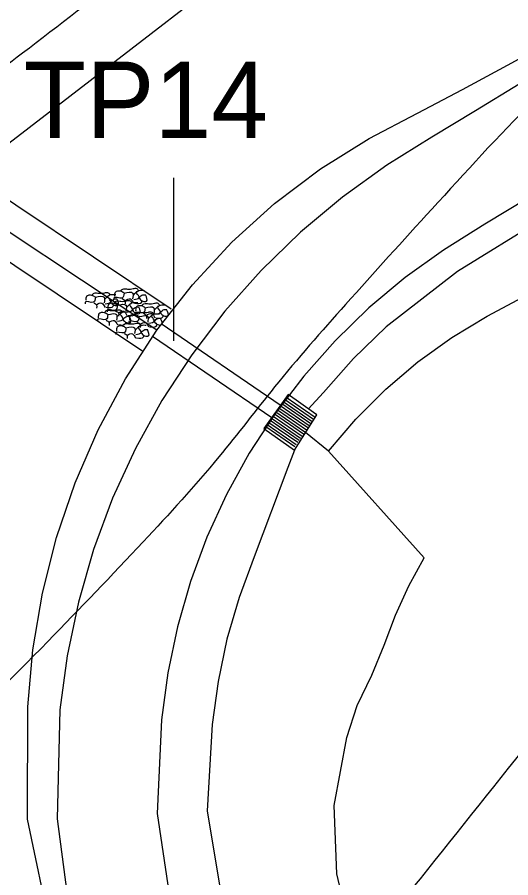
# Model space of a CAD drawing. Extents: x -478000 to -474772, y -1116847 to -1114124.
# Drawn here: x -476765.72 to -476746.36, y -1114902.02 to -1114868.23 of the extents above; entities that cross this region are included whole.
import ezdxf

# ---------------------------------------------------------------- set-up
doc = ezdxf.new("R2010")
doc.units = 0
for name, color, linetype in [('cestn___p____kop', 7, 'Continuous'), ('dren____', 7, 'Continuous'), ('hrana_L', 7, 'Continuous'), ('RozhraniKultur', 7, 'Continuous'), ('TP _navrh', 7, 'Continuous'), ('Vrstevnice_hlavni', 7, 'Continuous'), ('Vrstevnice_vedlejsi', 7, 'Continuous'), ('ZNACKY', 7, 'Continuous')]:
    doc.layers.add(name, color=color, linetype=linetype)

msp = doc.modelspace()

# ---------------------------------------------------------------- linework, layer by layer
at = {"layer": 'cestn___p____kop'}
for p, q in [((-476745.668, -1114875.318), (-476747.377, -1114876.357)), ((-476747.377, -1114876.357), (-476749.008, -1114877.372)), ((-476749.008, -1114877.372), (-476750.511, -1114878.453)), ((-476750.511, -1114878.453), (-476751.93, -1114879.641)), ((-476747.289, -1114879.961), (-476745.696, -1114879.121)), ((-476747.289, -1114879.961), (-476745.696, -1114879.121)), ((-476751.93, -1114879.641), (-476753.258, -1114880.932)), ((-476748.682, -1114880.808), (-476747.289, -1114879.961)), ((-476748.682, -1114880.808), (-476747.289, -1114879.961)), ((-476753.258, -1114880.932), (-476754.486, -1114882.317)), ((-476750.014, -1114881.764), (-476748.682, -1114880.808)), ((-476750.014, -1114881.764), (-476748.682, -1114880.808)), ((-476751.268, -1114882.833), (-476750.014, -1114881.764)), ((-476751.268, -1114882.833), (-476750.014, -1114881.764)), ((-476754.486, -1114882.317), (-476755.609, -1114883.79)), ((-476752.436, -1114884.004), (-476751.268, -1114882.833)), ((-476752.436, -1114884.004), (-476751.268, -1114882.833)), ((-476755.609, -1114883.79), (-476756.619, -1114885.341)), ((-476753.509, -1114885.27), (-476752.436, -1114884.004)), ((-476753.509, -1114885.27), (-476752.436, -1114884.004)), ((-476756.619, -1114885.341), (-476757.512, -1114886.963)), ((-476754.844, -1114885.23), (-476755.107, -1114885.904)), ((-476749.758, -1114889.456), (-476753.509, -1114885.27)), ((-476749.758, -1114889.456), (-476753.509, -1114885.27)), ((-476755.107, -1114885.904), (-476756.431, -1114889.412)), ((-476757.512, -1114886.963), (-476758.282, -1114888.647)), ((-476758.282, -1114888.647), (-476758.926, -1114890.383)), ((-476756.431, -1114889.412), (-476757.023, -1114891.009)), ((-476750.365, -1114890.559), (-476749.758, -1114889.456)), ((-476750.365, -1114890.559), (-476749.758, -1114889.456)), ((-476758.926, -1114890.383), (-476759.439, -1114892.162)), ((-476750.889, -1114891.704), (-476750.365, -1114890.559)), ((-476750.889, -1114891.704), (-476750.365, -1114890.559)), ((-476757.023, -1114891.009), (-476757.495, -1114892.645)), ((-476751.327, -1114892.884), (-476750.889, -1114891.704)), ((-476751.327, -1114892.884), (-476750.889, -1114891.704)), ((-476759.439, -1114892.162), (-476759.819, -1114893.973)), ((-476757.495, -1114892.645), (-476757.845, -1114894.312)), ((-476751.813, -1114894.06), (-476751.327, -1114892.884)), ((-476751.813, -1114894.06), (-476751.327, -1114892.884)), ((-476759.819, -1114893.973), (-476760.064, -1114895.809)), ((-476752.392, -1114895.247), (-476751.813, -1114894.06)), ((-476752.392, -1114895.247), (-476751.813, -1114894.06)), ((-476757.845, -1114894.312), (-476758.071, -1114896)), ((-476752.796, -1114896.507), (-476752.392, -1114895.247)), ((-476752.796, -1114896.507), (-476752.392, -1114895.247)), ((-476752.869, -1114903.183), (-476753.187, -1114901.86)), ((-476752.869, -1114903.183), (-476753.187, -1114901.86))]:
    msp.add_line(p, q, dxfattribs=at)
for points in [[(-476746.491, -1114870.118), (-476744.735, -1114869.156)], [(-476748.258, -1114871.062), (-476746.491, -1114870.118)], [(-476750.028, -1114872), (-476748.258, -1114871.062)], [(-476746.039, -1114870.861), (-476747.747, -1114871.9)], [(-476751.917, -1114872.99), (-476750.028, -1114872)], [(-476747.747, -1114871.9), (-476749.456, -1114872.94)], [(-476753.822, -1114874.188), (-476751.917, -1114872.99)], [(-476749.456, -1114872.94), (-476751.22, -1114874.04)], [(-476755.626, -1114875.548), (-476753.822, -1114874.188)], [(-476751.22, -1114874.04), (-476752.964, -1114875.293)], [(-476757.305, -1114877.067), (-476755.626, -1114875.548)], [(-476752.964, -1114875.293), (-476754.611, -1114876.672)], [(-476745.145, -1114876.177), (-476748.451, -1114878.211)], [(-476754.611, -1114876.672), (-476756.15, -1114878.169)], [(-476758.846, -1114878.731), (-476757.305, -1114877.067)], [(-476756.15, -1114878.169), (-476757.575, -1114879.776)], [(-476748.451, -1114878.211), (-476751.256, -1114880.389)], [(-476760.243, -1114880.521), (-476758.846, -1114878.731)], [(-476757.575, -1114879.776), (-476758.877, -1114881.484)], [(-476761.472, -1114882.431), (-476760.243, -1114880.521)], [(-476751.256, -1114880.389), (-476752.53, -1114881.627)], [(-476758.877, -1114881.484), (-476760.049, -1114883.284)], [(-476752.53, -1114881.627), (-476753.709, -1114882.957)], [(-476762.544, -1114884.431), (-476761.472, -1114882.431)], [(-476753.709, -1114882.957), (-476754.306, -1114883.614)], [(-476760.049, -1114883.284), (-476761.085, -1114885.165)], [(-476763.443, -1114886.513), (-476762.544, -1114884.431)], [(-476761.085, -1114885.165), (-476761.978, -1114887.118)], [(-476764.177, -1114888.654), (-476763.443, -1114886.513)], [(-476761.978, -1114887.118), (-476762.725, -1114889.132)], [(-476764.727, -1114890.846), (-476764.177, -1114888.654)], [(-476762.725, -1114889.132), (-476763.321, -1114891.196)], [(-476765.113, -1114893.066), (-476764.727, -1114890.846)], [(-476763.321, -1114891.196), (-476763.762, -1114893.297)], [(-476765.309, -1114895.305), (-476765.113, -1114893.066)], [(-476763.762, -1114893.297), (-476764.046, -1114895.426)], [(-476764.384, -1114904.135), (-476765.317, -1114899.72), (-476765.309, -1114895.305)], [(-476764.046, -1114895.426), (-476764.16, -1114899.701), (-476763.598, -1114903.976)], [(-476760.064, -1114895.809), (-476760.237, -1114899.494), (-476759.678, -1114903.179)], [(-476758.071, -1114896), (-476758.265, -1114899.39), (-476757.715, -1114902.78)], [(-476753.187, -1114901.86), (-476753.292, -1114899.184), (-476752.796, -1114896.507)], [(-476753.187, -1114901.86), (-476753.292, -1114899.184), (-476752.796, -1114896.507)]]:
    msp.add_lwpolyline(points, dxfattribs=at)
at = {"layer": 'dren____'}
for points in [[(-476761.672, -1114878.983), (-476761.582, -1114878.903), (-476761.39, -1114878.903), (-476761.169, -1114878.883), (-476761.033, -1114878.883), (-476760.976, -1114878.976), (-476761.05, -1114879.015)], [(-476762.653, -1114879.223), (-476762.73, -1114879.421), (-476763.054, -1114879.421), (-476763.054, -1114879.477)], [(-476762.653, -1114879.223), (-476762.789, -1114879.151), (-476763.002, -1114879.195), (-476763.026, -1114879.344)], [(-476762.791, -1114879.146), (-476762.702, -1114879.066), (-476762.51, -1114879.066), (-476762.289, -1114879.046), (-476762.152, -1114879.046), (-476762.096, -1114879.139), (-476762.17, -1114879.178)], [(-476762.653, -1114879.223), (-476762.314, -1114879.223), (-476762.314, -1114879.445)], [(-476762.282, -1114879.3), (-476762.052, -1114879.119), (-476761.855, -1114879.119)], [(-476762.27, -1114879.477), (-476762.056, -1114879.401), (-476762.161, -1114879.227)], [(-476761.533, -1114879.06), (-476761.611, -1114879.258), (-476761.934, -1114879.258), (-476761.934, -1114879.314)], [(-476761.533, -1114879.06), (-476761.669, -1114878.988), (-476761.882, -1114879.032), (-476761.906, -1114879.181)], [(-476761.533, -1114879.06), (-476761.194, -1114879.06), (-476761.194, -1114879.282)], [(-476761.498, -1114879.357), (-476761.283, -1114879.29), (-476761.158, -1114879.459)], [(-476761.162, -1114879.137), (-476760.933, -1114878.956), (-476760.736, -1114878.956)], [(-476761.15, -1114879.314), (-476760.937, -1114879.237), (-476761.041, -1114879.064)], [(-476760.943, -1114879.248), (-476760.788, -1114879.129), (-476760.691, -1114879.129)], [(-476760.943, -1114879.248), (-476760.8, -1114879.374), (-476760.647, -1114879.374), (-476760.691, -1114879.129)], [(-476762.72, -1114879.441), (-476762.608, -1114879.537), (-476762.608, -1114879.646)], [(-476762.618, -1114879.52), (-476762.402, -1114879.453), (-476762.278, -1114879.622)], [(-476762.237, -1114879.618), (-476761.96, -1114879.575), (-476761.944, -1114879.529)], [(-476761.794, -1114879.539), (-476761.871, -1114879.737), (-476762.195, -1114879.737), (-476762.195, -1114879.793)], [(-476761.794, -1114879.539), (-476761.93, -1114879.467), (-476762.143, -1114879.511), (-476762.167, -1114879.66)], [(-476762.063, -1114879.411), (-476761.908, -1114879.292), (-476761.811, -1114879.292)], [(-476762.063, -1114879.411), (-476761.92, -1114879.537), (-476761.767, -1114879.537), (-476761.811, -1114879.292)], [(-476761.932, -1114879.462), (-476761.842, -1114879.382), (-476761.651, -1114879.382), (-476761.43, -1114879.362), (-476761.293, -1114879.362), (-476761.236, -1114879.455), (-476761.31, -1114879.494)], [(-476761.794, -1114879.539), (-476761.455, -1114879.539), (-476761.455, -1114879.761)], [(-476761.601, -1114879.278), (-476761.488, -1114879.374), (-476761.488, -1114879.483)], [(-476761.423, -1114879.616), (-476761.193, -1114879.435), (-476760.996, -1114879.435)], [(-476761.41, -1114879.793), (-476761.197, -1114879.716), (-476761.302, -1114879.543)], [(-476761.204, -1114879.727), (-476761.048, -1114879.608), (-476760.952, -1114879.608)], [(-476761.204, -1114879.727), (-476761.06, -1114879.853), (-476760.908, -1114879.853), (-476760.952, -1114879.608)], [(-476761.118, -1114879.455), (-476760.84, -1114879.412), (-476760.825, -1114879.366)], [(-476760.702, -1114879.638), (-476760.839, -1114879.565), (-476761.052, -1114879.61), (-476761.075, -1114879.759)], [(-476760.841, -1114879.561), (-476760.751, -1114879.48), (-476760.559, -1114879.48), (-476760.339, -1114879.461), (-476760.202, -1114879.461), (-476760.145, -1114879.554), (-476760.219, -1114879.592)], [(-476760.702, -1114879.638), (-476760.364, -1114879.638), (-476760.364, -1114879.859)], [(-476760.331, -1114879.714), (-476760.102, -1114879.533), (-476759.905, -1114879.533)], [(-476762.167, -1114879.906), (-476762.244, -1114880.103), (-476762.568, -1114880.103), (-476762.568, -1114880.159)], [(-476762.167, -1114879.906), (-476762.303, -1114879.833), (-476762.516, -1114879.877), (-476762.54, -1114880.026)], [(-476762.305, -1114879.828), (-476762.216, -1114879.748), (-476762.024, -1114879.748), (-476761.803, -1114879.728), (-476761.666, -1114879.728), (-476761.61, -1114879.821), (-476761.684, -1114879.86)], [(-476762.167, -1114879.906), (-476761.828, -1114879.906), (-476761.828, -1114880.127)], [(-476761.861, -1114879.757), (-476761.748, -1114879.853), (-476761.748, -1114879.962)], [(-476761.796, -1114879.982), (-476761.566, -1114879.801), (-476761.369, -1114879.801)], [(-476761.784, -1114880.159), (-476761.57, -1114880.083), (-476761.675, -1114879.91)], [(-476761.759, -1114879.836), (-476761.543, -1114879.769), (-476761.419, -1114879.938)], [(-476761.378, -1114879.934), (-476761.101, -1114879.891), (-476761.085, -1114879.845)], [(-476760.942, -1114879.984), (-476761.078, -1114879.912), (-476761.291, -1114879.956), (-476761.315, -1114880.105)], [(-476760.702, -1114879.638), (-476760.78, -1114879.835), (-476761.104, -1114879.835), (-476761.104, -1114879.892)], [(-476761.08, -1114879.907), (-476760.991, -1114879.826), (-476760.799, -1114879.826), (-476760.578, -1114879.807), (-476760.442, -1114879.807), (-476760.385, -1114879.9), (-476760.459, -1114879.938)], [(-476760.942, -1114879.984), (-476760.603, -1114879.984), (-476760.603, -1114880.206)], [(-476760.77, -1114879.855), (-476760.657, -1114879.952), (-476760.657, -1114880.061)], [(-476760.668, -1114879.935), (-476760.452, -1114879.867), (-476760.327, -1114880.036)], [(-476760.571, -1114880.061), (-476760.342, -1114879.879), (-476760.145, -1114879.879)], [(-476760.319, -1114879.892), (-476760.106, -1114879.815), (-476760.211, -1114879.642)], [(-476760.287, -1114880.033), (-476760.01, -1114879.99), (-476759.994, -1114879.944)], [(-476760.112, -1114879.826), (-476759.957, -1114879.706), (-476759.861, -1114879.706)], [(-476760.112, -1114879.826), (-476759.969, -1114879.952), (-476759.816, -1114879.952), (-476759.861, -1114879.706)], [(-476762.234, -1114880.123), (-476762.121, -1114880.22), (-476762.121, -1114880.328)], [(-476762.132, -1114880.203), (-476761.916, -1114880.135), (-476761.792, -1114880.304)], [(-476761.751, -1114880.301), (-476761.474, -1114880.257), (-476761.458, -1114880.211)], [(-476761.594, -1114880.35), (-476761.504, -1114880.269), (-476761.313, -1114880.269), (-476761.092, -1114880.25), (-476760.955, -1114880.25), (-476760.898, -1114880.343), (-476760.972, -1114880.381)], [(-476761.577, -1114880.093), (-476761.422, -1114879.974), (-476761.325, -1114879.974)], [(-476761.577, -1114880.093), (-476761.434, -1114880.22), (-476761.281, -1114880.22), (-476761.325, -1114879.974)], [(-476760.942, -1114879.984), (-476761.02, -1114880.181), (-476761.343, -1114880.181), (-476761.343, -1114880.238)], [(-476761.009, -1114880.202), (-476760.897, -1114880.298), (-476760.897, -1114880.407)], [(-476760.907, -1114880.281), (-476760.692, -1114880.214), (-476760.567, -1114880.383)], [(-476760.559, -1114880.238), (-476760.346, -1114880.161), (-476760.45, -1114879.988)], [(-476760.352, -1114880.172), (-476760.197, -1114880.053), (-476760.1, -1114880.053)], [(-476760.352, -1114880.172), (-476760.209, -1114880.298), (-476760.056, -1114880.298), (-476760.1, -1114880.053)], [(-476761.456, -1114880.427), (-476761.533, -1114880.624), (-476761.857, -1114880.624), (-476761.857, -1114880.68)], [(-476761.456, -1114880.427), (-476761.592, -1114880.354), (-476761.805, -1114880.399), (-476761.829, -1114880.547)], [(-476761.456, -1114880.427), (-476761.117, -1114880.427), (-476761.117, -1114880.648)], [(-476761.085, -1114880.503), (-476760.855, -1114880.322), (-476760.658, -1114880.322)], [(-476761.073, -1114880.68), (-476760.859, -1114880.604), (-476760.964, -1114880.431)], [(-476760.866, -1114880.615), (-476760.711, -1114880.495), (-476760.614, -1114880.495)], [(-476760.866, -1114880.615), (-476760.723, -1114880.741), (-476760.57, -1114880.741), (-476760.614, -1114880.495)], [(-476760.527, -1114880.379), (-476760.249, -1114880.336), (-476760.234, -1114880.29)], [(-476761.523, -1114880.644), (-476761.41, -1114880.741), (-476761.41, -1114880.849)], [(-476761.421, -1114880.724), (-476761.205, -1114880.656), (-476761.081, -1114880.825)], [(-476761.04, -1114880.822), (-476760.763, -1114880.778), (-476760.747, -1114880.732)]]:
    msp.add_spline(points, degree=3, dxfattribs=at)
at = {"layer": 'hrana_L'}
for p, q in [((-476755.292, -1114883.312), (-476754.152, -1114884.096)), ((-476755.235, -1114883.23), (-476754.095, -1114884.014)), ((-476755.179, -1114883.147), (-476754.039, -1114883.931)), ((-476755.519, -1114883.642), (-476754.379, -1114884.426)), ((-476755.462, -1114883.559), (-476754.322, -1114884.343)), ((-476755.405, -1114883.477), (-476754.266, -1114884.261)), ((-476755.349, -1114883.394), (-476754.209, -1114884.178)), ((-476755.745, -1114883.971), (-476754.606, -1114884.755)), ((-476755.689, -1114883.889), (-476754.549, -1114884.673)), ((-476755.632, -1114883.806), (-476754.492, -1114884.59)), ((-476755.575, -1114883.724), (-476754.436, -1114884.508)), ((-476755.972, -1114884.301), (-476754.832, -1114885.085)), ((-476755.915, -1114884.218), (-476754.776, -1114885.002)), ((-476755.859, -1114884.136), (-476754.719, -1114884.92)), ((-476755.802, -1114884.053), (-476754.662, -1114884.838))]:
    msp.add_line(p, q, dxfattribs=at)
msp.add_lwpolyline([(-476754.107, -1114883.746), (-476755.098, -1114883.041), (-476756.046, -1114884.376), (-476754.844, -1114885.23), (-476753.975, -1114883.836)], close=True, dxfattribs=at)
at = {"layer": 'RozhraniKultur'}
msp.add_lwpolyline([(-476704.873, -1114837.784), (-476719.729, -1114846.758), (-476735.455, -1114853.116), (-476751.069, -1114861.62), (-476768.455, -1114875.027), (-476783.148, -1114888.825), (-476792.551, -1114896.585), (-476800.931, -1114901.838)], dxfattribs=at)
at = {"layer": 'Vrstevnice_hlavni'}
msp.add_spline([(-476703.206, -1114841.406), (-476711.621, -1114847.15), (-476714.865, -1114849.378), (-476717.146, -1114850.963), (-476718.462, -1114851.905), (-476720.571, -1114853.451), (-476723.472, -1114855.602), (-476727.165, -1114858.357), (-476730.809, -1114860.879), (-476734.404, -1114863.169), (-476737.95, -1114865.226), (-476741.641, -1114868.011), (-476745.477, -1114871.522), (-476749.458, -1114875.761), (-476752.841, -1114879.503), (-476755.626, -1114882.747), (-476757.813, -1114885.494), (-476760.779, -1114888.823), (-476764.523, -1114892.736), (-476769.046, -1114897.231), (-476772.788, -1114900.65), (-476775.75, -1114902.995), (-476777.931, -1114904.264), (-476780.372, -1114906.717), (-476783.074, -1114910.355), (-476786.036, -1114915.178), (-476788.079, -1114919.546), (-476789.204, -1114923.461), (-476789.411, -1114926.921), (-476790.703, -1114931.762), (-476793.079, -1114937.984), (-476796.539, -1114945.586), (-476799.078, -1114951.131), (-476800.696, -1114954.62), (-476801.392, -1114956.051), (-476801.982, -1114957.286), (-476802.466, -1114958.322), (-476802.843, -1114959.161), (-476803.085, -1114960.068), (-476803.189, -1114961.041), (-476803.157, -1114962.083), (-476802.788, -1114965.146), (-476802.083, -1114970.231), (-476801.041, -1114977.338), (-476800.104, -1114983.804), (-476799.272, -1114989.63), (-476798.543, -1114994.815), (-476797.724, -1114998.848), (-476796.815, -1115001.728), (-476795.815, -1115003.457), (-476792.972, -1115008.349), (-476788.286, -1115016.404), (-476775.228, -1115038.842)], degree=3, dxfattribs=at)
at = {"layer": 'Vrstevnice_vedlejsi'}
for points in [[(-476634.508, -1114799.611), (-476638.456, -1114801.4), (-476641.347, -1114802.725), (-476643.18, -1114803.587), (-476643.957, -1114803.987), (-476644.583, -1114804.362), (-476645.059, -1114804.713), (-476645.385, -1114805.041), (-476647.006, -1114806.225), (-476649.919, -1114808.266), (-476654.127, -1114811.165), (-476657.151, -1114813.409), (-476658.993, -1114814.999), (-476659.653, -1114815.934), (-476660.13, -1114816.58), (-476660.424, -1114816.937), (-476660.535, -1114817.005), (-476661.514, -1114817.82), (-476663.36, -1114819.383), (-476666.074, -1114821.693), (-476667.906, -1114823.241), (-476668.856, -1114824.027), (-476668.924, -1114824.05), (-476669.286, -1114824.232), (-476669.942, -1114824.573), (-476670.892, -1114825.071), (-476671.871, -1114825.807), (-476672.878, -1114826.78), (-476673.914, -1114827.991), (-476674.792, -1114829.124), (-476675.513, -1114830.181), (-476676.076, -1114831.161), (-476676.571, -1114832.38), (-476676.997, -1114833.838), (-476677.355, -1114835.535), (-476677.583, -1114836.811), (-476677.682, -1114837.668), (-476677.653, -1114838.104), (-476677.697, -1114838.556), (-476677.815, -1114839.023), (-476678.008, -1114839.506), (-476678.337, -1114840.041), (-476678.802, -1114840.629), (-476679.403, -1114841.269), (-476681.568, -1114842.933), (-476685.296, -1114845.622), (-476690.588, -1114849.336), (-476695.115, -1114852.493), (-476698.877, -1114855.095), (-476701.876, -1114857.141), (-476705.546, -1114859.702), (-476709.889, -1114862.776), (-476714.903, -1114866.363), (-476718.702, -1114869.095), (-476721.285, -1114870.971), (-476722.652, -1114871.99), (-476724, -1114872.924), (-476725.331, -1114873.771), (-476726.643, -1114874.533), (-476728.009, -1114875.563), (-476729.428, -1114876.863), (-476730.902, -1114878.431), (-476734.953, -1114883.332), (-476741.583, -1114891.565), (-476750.792, -1114903.131), (-476757.182, -1114911.091), (-476760.755, -1114915.446), (-476761.511, -1114916.197), (-476762.136, -1114916.768), (-476762.63, -1114917.16), (-476762.995, -1114917.372), (-476763.402, -1114917.782), (-476763.854, -1114918.389), (-476764.348, -1114919.195), (-476764.898, -1114923.418), (-476765.504, -1114931.058), (-476766.165, -1114942.116), (-476766.951, -1114950.246), (-476767.862, -1114955.449), (-476768.898, -1114957.725), (-476768.625, -1114963.546), (-476767.043, -1114972.913), (-476764.152, -1114985.826), (-476762.205, -1114994.575), (-476761.202, -1114999.16), (-476761.143, -1114999.58), (-476760.983, -1115000.068), (-476760.722, -1115000.624), (-476760.361, -1115001.249), (-476758.688, -1115004.469), (-476755.702, -1115010.284), (-476751.405, -1115018.696), (-476745.736, -1115025.736), (-476738.696, -1115031.405), (-476730.284, -1115035.702), (-476724.55, -1115038.648), (-476721.491, -1115040.243)], [(-476699.302, -1114807.738), (-476700.061, -1114807.417), (-476700.791, -1114807.137), (-476701.493, -1114806.901), (-476702.167, -1114806.706), (-476702.755, -1114806.595), (-476703.256, -1114806.567), (-476703.672, -1114806.623), (-476704.219, -1114806.707), (-476704.898, -1114806.821), (-476705.708, -1114806.964), (-476706.254, -1114807.059), (-476706.537, -1114807.106), (-476706.555, -1114807.106), (-476706.6, -1114807.112), (-476706.671, -1114807.126), (-476706.769, -1114807.147), (-476706.801, -1114807.178), (-476706.766, -1114807.22), (-476706.665, -1114807.273), (-476706.424, -1114807.4), (-476706.043, -1114807.6), (-476705.52, -1114807.874), (-476705.069, -1114808.321), (-476704.688, -1114808.941), (-476704.378, -1114809.733), (-476704.228, -1114810.381), (-476704.238, -1114810.882), (-476704.408, -1114811.239), (-476704.185, -1114811.849), (-476703.568, -1114812.712), (-476702.557, -1114813.829), (-476701.865, -1114814.603), (-476701.491, -1114815.034), (-476701.436, -1114815.122), (-476701.388, -1114815.197), (-476701.345, -1114815.261), (-476701.309, -1114815.312), (-476701.321, -1114815.35), (-476701.381, -1114815.373), (-476701.488, -1114815.383), (-476703.025, -1114815.387), (-476705.991, -1114815.384), (-476710.387, -1114815.374), (-476713.753, -1114816.768), (-476716.089, -1114819.566), (-476717.396, -1114823.766), (-476718.59, -1114827.172), (-476719.67, -1114829.784), (-476720.637, -1114831.601), (-476721.448, -1114833.126), (-476722.102, -1114834.361), (-476722.6, -1114835.305), (-476722.997, -1114836.519), (-476723.294, -1114838.005), (-476723.489, -1114839.762), (-476723.817, -1114841.162), (-476724.278, -1114842.206), (-476724.871, -1114842.892), (-476725.796, -1114843.684), (-476727.052, -1114844.581), (-476728.64, -1114845.583), (-476730.295, -1114846.615), (-476732.018, -1114847.677), (-476733.81, -1114848.768), (-476735.678, -1114849.816), (-476737.624, -1114850.82), (-476739.646, -1114851.78), (-476741.962, -1114852.973), (-476744.572, -1114854.399), (-476747.476, -1114856.058), (-476750.141, -1114857.756), (-476752.567, -1114859.491), (-476754.755, -1114861.264), (-476757.642, -1114863.548), (-476761.227, -1114866.341), (-476765.511, -1114869.645), (-476768.802, -1114872.166), (-476771.101, -1114873.906), (-476772.408, -1114874.864), (-476774.448, -1114876.79), (-476777.221, -1114879.686), (-476780.727, -1114883.552), (-476783.192, -1114886.256), (-476784.615, -1114887.799), (-476784.996, -1114888.181), (-476786.178, -1114889.079), (-476788.16, -1114890.492), (-476790.943, -1114892.42), (-476792.957, -1114893.912), (-476794.2, -1114894.967), (-476794.673, -1114895.584), (-476795.717, -1114896.452), (-476797.332, -1114897.571), (-476799.517, -1114898.941), (-476801.16, -1114900.037), (-476802.262, -1114900.859)], [(-476802.262, -1114900.859), (-476802.823, -1114901.408), (-476804.324, -1114902.62), (-476806.767, -1114904.496), (-476810.152, -1114907.036), (-476812.719, -1114909.363), (-476814.468, -1114911.478), (-476815.401, -1114913.381), (-476816.38, -1114915.236), (-476817.406, -1114917.044), (-476818.48, -1114918.803), (-476819.736, -1114921.088), (-476821.175, -1114923.897), (-476822.795, -1114927.233), (-476825.349, -1114932.726), (-476828.836, -1114940.379), (-476833.255, -1114950.189), (-476836.075, -1114960.79), (-476837.297, -1114972.18), (-476836.919, -1114984.361), (-476836.611, -1114992.865), (-476836.372, -1114997.694), (-476836.203, -1114998.847), (-476834.237, -1115001.766), (-476830.474, -1115006.451), (-476824.913, -1115012.901), (-476820.082, -1115019.496), (-476815.982, -1115026.235), (-476812.612, -1115033.117), (-476809.338, -1115038.968), (-476806.161, -1115043.785), (-476803.08, -1115047.571), (-476798.138, -1115053.277), (-476791.333, -1115060.904), (-476782.667, -1115070.452), (-476775.571, -1115078.872), (-476770.046, -1115086.164), (-476766.092, -1115092.329), (-476763.218, -1115097.232), (-476761.425, -1115100.873), (-476760.713, -1115103.254), (-476759.695, -1115105.894), (-476758.373, -1115108.796), (-476756.746, -1115111.958), (-476755.389, -1115114.608), (-476754.3, -1115116.746), (-476753.481, -1115118.373), (-476752.634, -1115119.794), (-476751.76, -1115121.01), (-476750.858, -1115122.02), (-476749.617, -1115123.346), (-476748.037, -1115124.989), (-476746.118, -1115126.948), (-476744.198, -1115128.586), (-476742.277, -1115129.902), (-476740.356, -1115130.897), (-476737.026, -1115134.06), (-476732.29, -1115139.393), (-476726.145, -1115146.893), (-476721.618, -1115152.517), (-476718.709, -1115156.263), (-476717.417, -1115158.131), (-476714, -1115163.455), (-476708.456, -1115172.232), (-476700.787, -1115184.465), (-476695.651, -1115192.648), (-476693.051, -1115196.783), (-476692.984, -1115196.869), (-476692.929, -1115196.966), (-476692.887, -1115197.075), (-476692.855, -1115197.196), (-476691.289, -1115198.947), (-476688.186, -1115202.329), (-476683.548, -1115207.341), (-476680.069, -1115210.815), (-476677.751, -1115212.753), (-476676.591, -1115213.154), (-476675.177, -1115213.688), (-476673.508, -1115214.356), (-476671.583, -1115215.157), (-476670.137, -1115215.762), (-476669.169, -1115216.169), (-476668.678, -1115216.378), (-476668.279, -1115216.545), (-476667.972, -1115216.668), (-476667.757, -1115216.748), (-476667.546, -1115216.875), (-476667.339, -1115217.05), (-476667.137, -1115217.272), (-476665.829, -1115218.823), (-476663.416, -1115221.703), (-476659.897, -1115225.912), (-476657.133, -1115228.823), (-476655.122, -1115230.435), (-476653.866, -1115230.749), (-476652.725, -1115230.915), (-476651.7, -1115230.934)]]:
    msp.add_spline(points, degree=3, dxfattribs=at)
at = {"layer": 'ZNACKY'}
for p, q in [((-476759.578, -1114880.931), (-476759.578, -1114874.539)), ((-476755.403, -1114883.461), (-476760.074, -1114880.273)), ((-476755.741, -1114883.956), (-476760.412, -1114880.769)), ((-476753.509, -1114885.27), (-476754.409, -1114884.533))]:
    msp.add_line(p, q, dxfattribs=at)
for points in [[(-476759.687, -1114879.69), (-476768.836, -1114873.569)], [(-476760.243, -1114880.521), (-476769.087, -1114874.651), (-476794.855, -1114875.096)], [(-476760.799, -1114881.352), (-476769.183, -1114875.743), (-476769.183, -1114875.743)]]:
    msp.add_lwpolyline(points, dxfattribs=at)

# ---------------------------------------------------------------- texts
at = {"layer": 'TP _navrh'}
msp.add_text('TP14', height=3, rotation=360, dxfattribs=at).set_placement((-476765.468, -1114872.97))

doc.saveas('drawing.dxf')
